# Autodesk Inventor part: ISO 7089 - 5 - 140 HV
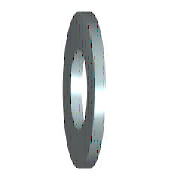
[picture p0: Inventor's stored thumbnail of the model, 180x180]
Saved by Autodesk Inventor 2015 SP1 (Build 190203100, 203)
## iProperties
Created: 2014-02
Part Number: ISO 7089 - 5 - 140 HV
Material: Stainless Steel
Description: Plain washers - Normal series - Product grade A
Document SubType Name: Modeling
Standard: ISO 7089
Designer: davidvaughan
Standard Revision: Second edition 2000-06-01
Standards Organization: ISO
Language: en-US
Size Designation: 5 - 140 HV
Categories: <MemberInstance><Categories><Category DisplayName="Fasteners" InternalName="e4da775c-781d-43d5-af7c-5136215cf5a6" Mnemonic="FSTN"><Category DisplayName="Washers
Density: 8 g/cm^3
Appearance: Semi-Polished
IsCustomPart: 1
Author: davidvaughan
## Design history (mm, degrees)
sketch "Sketch"
  geometry: C1 r 5 at (0, 0); C2 r 2.65 at (0, 0); 1 further point
  constraints: 2 centre point, 2 coincident
  dimensions: "d0" = 5.3 diameter of C2 (= SD1); "d1" = 10 diameter of C1 (= SD2)
extrude "Body" new body sketch "Sketch" distance "d2" = 1 (= SD); taper "d3" = 0 deg
workaxis "Work Axis1"
workplane "Work Plane1"
body "Solid1"
other parameters: "SD1" = 5.3 [user parameter; used in 1 equation term], "SD2" = 10 [user parameter; used in 1 equation term], "SD" = 1 [user parameter; used in 1 equation term], "d4" = 0, "d5" = 0, "d6" = 0, "d7" = 0, "NND" = 5 [user parameter]
